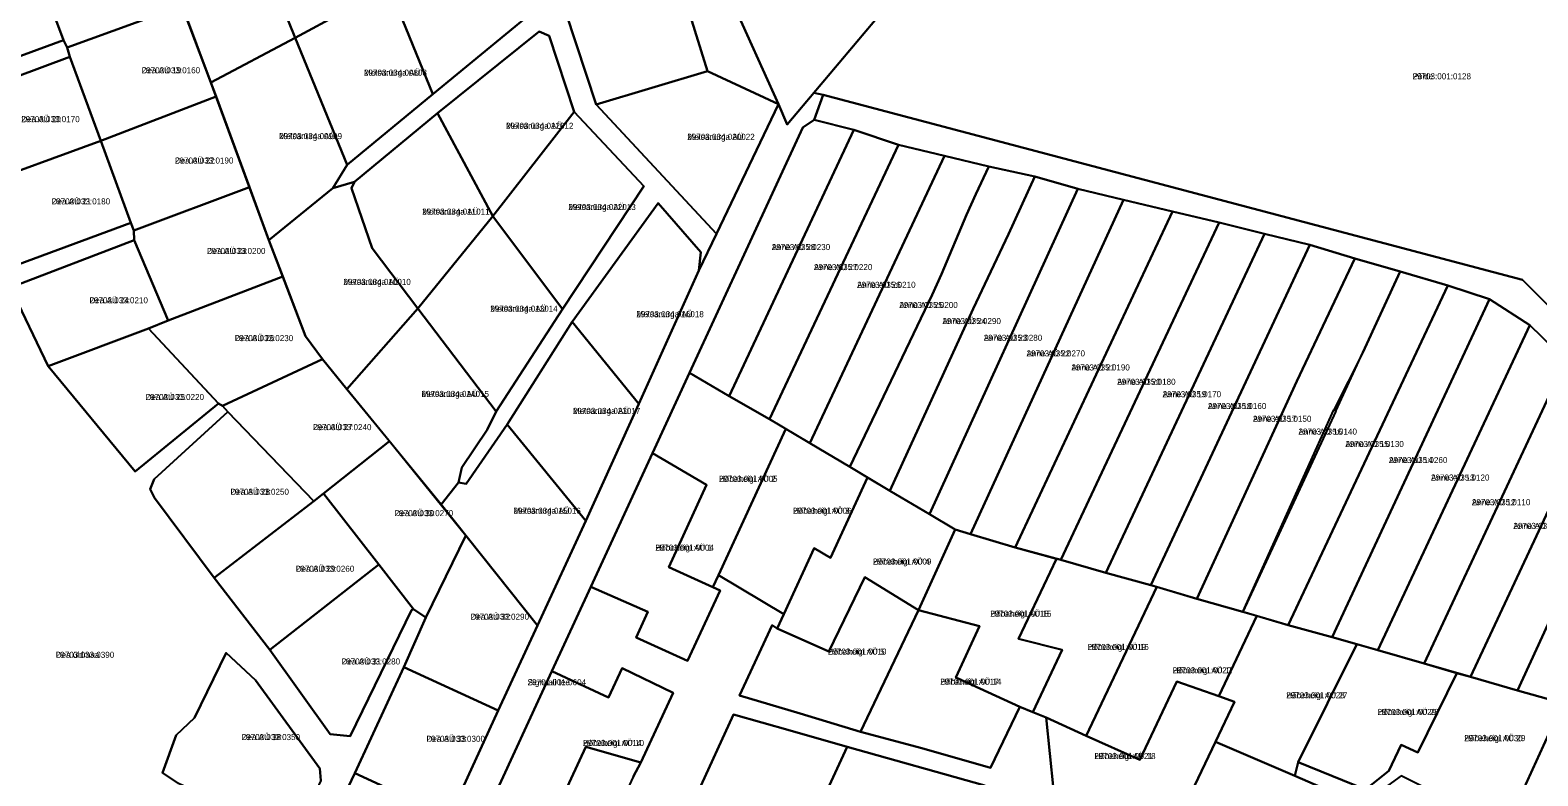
# Model space of a CAD drawing. Extents: x 504287 to 537970, y 6539941 to 6586214.
# Drawn here: x 518541.3 to 518915.2, y 6560366.3 to 6560551.4 of the extents above; entities that cross this region are included whole.
import ezdxf

# ---------------------------------------------------------------- set-up
doc = ezdxf.new("R2010")
doc.units = 0
for name, color, linetype in [('L_AADRESS', 7, 'Continuous'), ('PIIR', 7, 'Continuous'), ('TUNNUS', 7, 'Continuous')]:
    doc.layers.add(name, color=color, linetype=linetype)

msp = doc.modelspace()

# ---------------------------------------------------------------- linework, layer by layer
at = {"layer": 'PIIR'}
for points in [[(518652.65, 6560733.81), (518738.83, 6560735.38), (518768.89, 6560651.51), (518836.98, 6560656.24), (518729.02, 6560528.02), (518726.84, 6560533.06), (518680.26, 6560636.35), (518582.38, 6560628.09), (518581.74, 6560638.53), (518567.45, 6560635.3), (518576.36, 6560731.36)], [(519044.14, 6560671.72), (519015.49, 6560406.67), (518970.14, 6560431.7), (518959.47, 6560439.36), (518957.6, 6560442.94), (518911.37, 6560489.4), (518737.92, 6560535.32), (518735.63, 6560535.87), (518836.98, 6560656.24), (518890.66, 6560660.58)], [(518680.26, 6560636.35), (518726.84, 6560533.06), (518709.24, 6560541.19), (518699.85, 6560571.56), (518690.71, 6560600.29), (518681.74, 6560628.36), (518653.33, 6560625.81), (518651.06, 6560633.89)], [(518594.15, 6560581.53), (518620.85, 6560589.68), (518630.3, 6560562.19), (518607, 6560549.49)], [(518571.17, 6560578.12), (518588.78, 6560582.73), (518594.15, 6560581.53), (518607, 6560549.49), (518586.13, 6560538.4)], [(518570.54, 6560579.83), (518571.17, 6560578.12), (518578.95, 6560557.46), (518550.43, 6560547.09), (518549.54, 6560548.94), (518542.01, 6560569.21)], [(518630.3, 6560562.19), (518660.95, 6560578.68), (518667.13, 6560557.74), (518665.26, 6560555.4), (518641.13, 6560535.55)], [(518671.62, 6560563.35), (518699.85, 6560571.56), (518709.24, 6560541.19), (518681.68, 6560532.97)], [(518510.38, 6560557.54), (518539.53, 6560568.37), (518542.01, 6560569.21), (518549.54, 6560548.94), (518517.73, 6560537.23)], [(518607, 6560549.49), (518630.3, 6560562.19), (518641.13, 6560535.55), (518619.9, 6560517.97)], [(518551.09, 6560544.8), (518550.43, 6560547.09), (518578.95, 6560557.46), (518586.13, 6560538.4), (518587.42, 6560534.89), (518558.82, 6560523.93)], [(518586.13, 6560538.4), (518607, 6560549.49), (518619.9, 6560517.97), (518616.36, 6560512.18), (518600.49, 6560499.28)], [(518642.34, 6560530.81), (518667.51, 6560551.06), (518670.01, 6560550), (518676.23, 6560531.13), (518656.02, 6560505.19)], [(518519.54, 6560532.6), (518524.22, 6560534.79), (518551.09, 6560544.8), (518558.82, 6560523.93), (518527.08, 6560512.32)], [(518709.24, 6560541.19), (518726.84, 6560533.06), (518711.5, 6560500.83), (518681.68, 6560532.97)], [(518566.29, 6560503.6), (518558.82, 6560523.93), (518587.42, 6560534.89), (518595.68, 6560512.4), (518567.03, 6560501.7)], [(518626.14, 6560497.31), (518620.99, 6560512.17), (518621.74, 6560513.71), (518642.34, 6560530.81), (518656.02, 6560505.19), (518637.45, 6560482.3)], [(518656.02, 6560505.19), (518676.23, 6560531.13), (518693.48, 6560512.65), (518673.35, 6560482.14)], [(518704.81, 6560466.36), (518732.9, 6560527.21), (518735.69, 6560529.13), (518745.58, 6560526.65), (518714.64, 6560460.56)], [(518714.64, 6560460.56), (518745.58, 6560526.65), (518756.67, 6560522.93), (518724.67, 6560454.85)], [(518534.3, 6560492.74), (518527.08, 6560512.32), (518558.82, 6560523.93), (518566.29, 6560503.6), (518536.06, 6560492.38)], [(518724.67, 6560454.85), (518756.67, 6560522.93), (518768.08, 6560520.21), (518734.67, 6560448.85)], [(518734.67, 6560448.85), (518768.08, 6560520.21), (518779.01, 6560517.55), (518775.86, 6560510.72), (518773.47, 6560505.55), (518767.34, 6560490.86), (518764.96, 6560485.68), (518744.59, 6560443.03)], [(518744.59, 6560443.03), (518764.96, 6560485.68), (518767.34, 6560490.86), (518773.47, 6560505.55), (518775.86, 6560510.72), (518779.01, 6560517.55), (518790.49, 6560515.05), (518783.91, 6560500.78), (518775.17, 6560482.22), (518754.5, 6560437.02)], [(518754.5, 6560437.02), (518775.17, 6560482.22), (518783.91, 6560500.78), (518790.49, 6560515.05), (518801.08, 6560511.99), (518764.34, 6560431.24)], [(518567.07, 6560499.24), (518567.03, 6560501.7), (518595.68, 6560512.4), (518600.49, 6560499.28), (518603.94, 6560490.25), (518575.55, 6560479.31)], [(518613.8, 6560469.75), (518609.6, 6560475.44), (518600.49, 6560499.28), (518616.36, 6560512.18), (518621.74, 6560513.71), (518620.99, 6560512.17), (518626.14, 6560497.31), (518637.45, 6560482.3), (518619.86, 6560462.33)], [(518770.67, 6560427.42), (518764.34, 6560431.24), (518801.08, 6560511.99), (518812.44, 6560509.31), (518774.47, 6560426.3)], [(518697.06, 6560508.42), (518707.59, 6560496.29), (518707.15, 6560491.75), (518692.22, 6560458.64), (518675.67, 6560479.01)], [(518774.47, 6560426.3), (518812.44, 6560509.31), (518824.58, 6560506.39), (518785.58, 6560422.96)], [(518656.02, 6560505.19), (518673.35, 6560482.14), (518656.83, 6560456.71), (518637.45, 6560482.3)], [(518785.58, 6560422.96), (518824.58, 6560506.39), (518836.14, 6560503.63), (518796.88, 6560419.89)], [(518796.88, 6560419.89), (518836.14, 6560503.63), (518847.42, 6560500.85), (518808.08, 6560416.73)], [(518808.08, 6560416.73), (518847.42, 6560500.85), (518858.66, 6560498.13), (518819.25, 6560413.63)], [(518536.41, 6560487.5), (518567.07, 6560499.24), (518575.55, 6560479.31), (518570.63, 6560477.35), (518545.74, 6560467.99)], [(518819.25, 6560413.63), (518858.66, 6560498.13), (518869.82, 6560494.75), (518855.41, 6560464.24), (518830.65, 6560410.26)], [(518830.65, 6560410.26), (518855.41, 6560464.24), (518869.82, 6560494.75), (518881.04, 6560491.52), (518871.84, 6560471.37), (518864.62, 6560457.17), (518865.07, 6560456.86), (518842.05, 6560406.99)], [(518587.96, 6560458.72), (518570.63, 6560477.35), (518575.55, 6560479.31), (518603.94, 6560490.25), (518609.6, 6560475.44), (518613.8, 6560469.75), (518589.01, 6560458.16)], [(518842.05, 6560406.99), (518864.62, 6560457.17), (518865.07, 6560456.86), (518871.84, 6560471.37), (518881.04, 6560491.52), (518892.89, 6560488.03), (518853.32, 6560403.74)], [(518853.32, 6560403.74), (518892.89, 6560488.03), (518903.22, 6560484.64), (518864.2, 6560400.76)], [(518637.45, 6560482.3), (518656.83, 6560456.71), (518654.62, 6560452.19), (518648.35, 6560442.83), (518647.52, 6560439.11), (518643.18, 6560433.67), (518619.86, 6560462.33)], [(518864.2, 6560400.76), (518903.22, 6560484.64), (518913.23, 6560478.2), (518875.53, 6560397.55)], [(518675.67, 6560479.01), (518692.22, 6560458.64), (518679.09, 6560429.64), (518659.55, 6560453.54)], [(518875.53, 6560397.55), (518913.23, 6560478.2), (518922.14, 6560469.49), (518886.99, 6560394.2)], [(518570.63, 6560477.35), (518587.96, 6560458.72), (518567.36, 6560441.84), (518545.74, 6560467.99)], [(518590.27, 6560456.69), (518589.01, 6560458.16), (518613.8, 6560469.75), (518619.86, 6560462.33), (518630.42, 6560449.4), (518614.03, 6560436.37), (518611.67, 6560434.49)], [(518714.64, 6560460.56), (518724.67, 6560454.85), (518728.68, 6560452.44), (518711.96, 6560416.15), (518710.56, 6560413.13), (518699.64, 6560418.11), (518709.06, 6560438.54), (518695.6, 6560446.38), (518704.81, 6560466.36)], [(518886.99, 6560394.2), (518922.14, 6560469.49), (518931.28, 6560460.86), (518898.48, 6560390.85)], [(518898.48, 6560390.85), (518931.28, 6560460.86), (518939.85, 6560452.15), (518910.17, 6560387.5)], [(518572.14, 6560435.35), (518571.07, 6560437.47), (518572.02, 6560439.92), (518590.27, 6560456.69), (518611.67, 6560434.49), (518586.89, 6560415.45)], [(518647.52, 6560439.11), (518649.44, 6560438.81), (518659.55, 6560453.54), (518679.09, 6560429.64), (518667.09, 6560403.65), (518643.18, 6560433.67)], [(518734.67, 6560448.85), (518744.59, 6560443.03), (518748.99, 6560440.36), (518739.74, 6560420.4), (518735.72, 6560422.81), (518728.24, 6560406.48), (518711.96, 6560416.15), (518728.68, 6560452.44)], [(518910.17, 6560387.5), (518939.85, 6560452.15), (518948.27, 6560440.01), (518921.41, 6560384.38)], [(518614.03, 6560436.37), (518630.42, 6560449.4), (518649.34, 6560425.93), (518639.39, 6560405.63), (518636.38, 6560407.67), (518627.76, 6560418.77)], [(518695.6, 6560446.38), (518709.06, 6560438.54), (518699.64, 6560418.11), (518710.56, 6560413.13), (518712.38, 6560412.29), (518704.31, 6560394.84), (518691.57, 6560400.65), (518694.51, 6560407), (518680.32, 6560413.23)], [(518754.5, 6560437.02), (518764.34, 6560431.24), (518770.67, 6560427.42), (518761.6, 6560407.45), (518748.32, 6560415.6), (518739.36, 6560397.16), (518726.57, 6560402.85), (518728.24, 6560406.48), (518735.72, 6560422.81), (518739.74, 6560420.4), (518748.99, 6560440.36)], [(518586.89, 6560415.45), (518611.67, 6560434.49), (518614.03, 6560436.37), (518627.76, 6560418.77), (518600.7, 6560397.57)], [(518639.39, 6560405.63), (518649.34, 6560425.93), (518667.09, 6560403.65), (518657.34, 6560382.53), (518633.92, 6560393.33)], [(518774.47, 6560426.3), (518785.58, 6560422.96), (518795.84, 6560420.17), (518786.4, 6560400.3), (518797.22, 6560397.63), (518789.99, 6560382.08), (518786.77, 6560383.45), (518770.87, 6560390.76), (518776.77, 6560403.46), (518761.6, 6560407.45), (518770.67, 6560427.42)], [(518600.7, 6560397.57), (518627.76, 6560418.77), (518636.38, 6560407.67), (518635.82, 6560407.45), (518620.67, 6560376.18), (518615.7, 6560376.63)], [(518796.88, 6560419.89), (518808.08, 6560416.73), (518819.25, 6560413.63), (518820.7, 6560413.2), (518803.15, 6560376.28), (518793.26, 6560380.83), (518789.99, 6560382.08), (518797.22, 6560397.63), (518786.4, 6560400.3), (518795.84, 6560420.17)], [(518726.57, 6560402.85), (518739.36, 6560397.16), (518748.32, 6560415.6), (518761.6, 6560407.45), (518747.23, 6560377.21), (518732.23, 6560381.8), (518717.19, 6560386.27), (518725.34, 6560403.71)], [(518830.65, 6560410.26), (518842.05, 6560406.99), (518845.49, 6560405.99), (518836.1, 6560386.09), (518825.65, 6560389.77), (518816.49, 6560370.32), (518803.15, 6560376.28), (518820.7, 6560413.2)], [(518776.77, 6560403.46), (518770.87, 6560390.76), (518786.77, 6560383.45), (518779.44, 6560368.31), (518762.39, 6560373.16), (518747.23, 6560377.21), (518761.6, 6560407.45)], [(518853.32, 6560403.74), (518864.2, 6560400.76), (518870.35, 6560399.02), (518855.79, 6560369.73), (518854.93, 6560366.34), (518835.24, 6560374.79), (518839.98, 6560384.72), (518836.1, 6560386.09), (518845.49, 6560405.99)], [(518875.53, 6560397.55), (518886.99, 6560394.2), (518895.15, 6560391.82), (518885.42, 6560372.09), (518881.34, 6560374.03), (518878.27, 6560367.52), (518872.47, 6560362.92), (518855.79, 6560369.73), (518870.35, 6560399.02)], [(518574.08, 6560367.07), (518577.52, 6560376.41), (518582.01, 6560380.74), (518589.9, 6560396.82), (518597.19, 6560390.03), (518613.13, 6560368.1), (518613.39, 6560365.17), (518607.93, 6560353.29), (518605.66, 6560352.86), (518605.14, 6560351.85), (518578.07, 6560364.39)], [(518633.92, 6560393.33), (518657.34, 6560382.53), (518645.29, 6560356.18), (518621.81, 6560366.95)], [(518684.73, 6560385.78), (518688.11, 6560393.03), (518700.72, 6560386.95), (518692.72, 6560369.61), (518679.09, 6560373.49), (518670.29, 6560354.42), (518655.2, 6560358.71), (518670.68, 6560392.32)], [(518898.48, 6560390.85), (518910.17, 6560387.5), (518921.41, 6560384.38), (518907.28, 6560353.45), (518881.27, 6560366.28), (518875.3, 6560361.91), (518872.47, 6560362.92), (518878.27, 6560367.52), (518881.34, 6560374.03), (518885.42, 6560372.09), (518895.15, 6560391.82)], [(518803.15, 6560376.28), (518816.49, 6560370.32), (518825.65, 6560389.77), (518836.1, 6560386.09), (518839.98, 6560384.72), (518835.24, 6560374.79), (518824.05, 6560351.19), (518811.04, 6560358.67), (518795.1, 6560362.92), (518793.26, 6560380.83)], [(518729.79, 6560377.53), (518743.88, 6560373.55), (518734.51, 6560353.12), (518727.57, 6560338.2), (518713.26, 6560342.33), (518720.89, 6560357.71), (518706.71, 6560361.85), (518715.68, 6560381.57)], [(518692.72, 6560369.61), (518690.85, 6560366.04), (518683.7, 6560350.58), (518679.66, 6560351.85), (518670.12, 6560331.42), (518660.35, 6560334.15), (518645.78, 6560338.28), (518655.2, 6560358.71), (518670.29, 6560354.42), (518679.09, 6560373.49)], [(518734.51, 6560353.12), (518743.88, 6560373.55), (518778.03, 6560363.92), (518768.66, 6560343.46), (518753.52, 6560347.69)], [(518854.93, 6560366.34), (518864.63, 6560362.14), (518853.89, 6560339.57), (518837.55, 6560345.86), (518824.05, 6560351.19), (518835.24, 6560374.79)], [(518621.81, 6560366.95), (518645.29, 6560356.18), (518632.92, 6560329.34), (518609.27, 6560340.6)]]:
    msp.add_lwpolyline(points, close=True, dxfattribs=at)
for points in [[(518671.62, 6560563.35), (518681.68, 6560532.97), (518711.5, 6560500.83), (518707.15, 6560491.75), (518707.59, 6560496.29), (518697.06, 6560508.42), (518675.67, 6560479.01), (518659.55, 6560453.54), (518649.44, 6560438.81), (518647.52, 6560439.11), (518648.35, 6560442.83), (518654.62, 6560452.19), (518656.83, 6560456.71), (518673.35, 6560482.14), (518693.48, 6560512.65), (518676.23, 6560531.13), (518670.01, 6560550), (518667.51, 6560551.06), (518642.34, 6560530.81), (518621.74, 6560513.71), (518616.36, 6560512.18), (518619.9, 6560517.97), (518641.13, 6560535.55), (518665.26, 6560555.4)], [(518517.73, 6560537.23), (518549.54, 6560548.94), (518550.43, 6560547.09), (518551.09, 6560544.8), (518524.22, 6560534.79)], [(518645.29, 6560356.18), (518657.34, 6560382.53), (518667.09, 6560403.65), (518679.09, 6560429.64), (518692.22, 6560458.64), (518707.15, 6560491.75), (518711.5, 6560500.83), (518726.84, 6560533.06), (518729.02, 6560528.02), (518735.63, 6560535.87), (518737.92, 6560535.32), (518735.69, 6560529.13), (518732.9, 6560527.21), (518704.81, 6560466.36), (518695.6, 6560446.38), (518680.32, 6560413.23), (518670.68, 6560392.32), (518655.2, 6560358.71)], [(518922.14, 6560469.49), (518913.23, 6560478.2), (518903.22, 6560484.64), (518892.89, 6560488.03), (518881.04, 6560491.52), (518869.82, 6560494.75), (518858.66, 6560498.13), (518847.42, 6560500.85), (518836.14, 6560503.63), (518824.58, 6560506.39), (518812.44, 6560509.31), (518801.08, 6560511.99), (518790.49, 6560515.05), (518779.01, 6560517.55), (518768.08, 6560520.21), (518756.67, 6560522.93), (518745.58, 6560526.65), (518735.69, 6560529.13), (518737.92, 6560535.32), (518911.37, 6560489.4), (518957.6, 6560442.94)], [(518536.06, 6560492.38), (518566.29, 6560503.6), (518567.03, 6560501.7), (518567.07, 6560499.24), (518536.41, 6560487.5), (518545.74, 6560467.99), (518567.36, 6560441.84), (518587.96, 6560458.72), (518589.01, 6560458.16), (518590.27, 6560456.69), (518572.02, 6560439.92), (518571.07, 6560437.47), (518572.14, 6560435.35), (518586.89, 6560415.45), (518600.7, 6560397.57), (518615.7, 6560376.63), (518620.67, 6560376.18), (518635.82, 6560407.45), (518636.38, 6560407.67), (518639.39, 6560405.63), (518633.92, 6560393.33), (518621.81, 6560366.95), (518609.27, 6560340.6)], [(518690.85, 6560366.04), (518692.72, 6560369.61), (518700.72, 6560386.95), (518688.11, 6560393.03), (518684.73, 6560385.78), (518670.68, 6560392.32), (518680.32, 6560413.23), (518694.51, 6560407), (518691.57, 6560400.65), (518704.31, 6560394.84), (518712.38, 6560412.29), (518710.56, 6560413.13), (518711.96, 6560416.15), (518728.24, 6560406.48), (518726.57, 6560402.85), (518725.34, 6560403.71), (518717.19, 6560386.27), (518732.23, 6560381.8), (518747.23, 6560377.21), (518762.39, 6560373.16), (518779.44, 6560368.31), (518786.77, 6560383.45), (518789.99, 6560382.08), (518793.26, 6560380.83), (518795.1, 6560362.92)], [(518613.39, 6560365.17), (518613.13, 6560368.1), (518597.19, 6560390.03), (518589.9, 6560396.82), (518582.01, 6560380.74), (518577.52, 6560376.41), (518574.08, 6560367.07), (518578.07, 6560364.39)], [(518917.15, 6560359.22), (518911.58, 6560346.96), (518905.86, 6560334.63), (518900.2, 6560322.05), (518893.93, 6560324.21), (518921.41, 6560384.38)], [(518778.03, 6560363.92), (518743.88, 6560373.55), (518729.79, 6560377.53), (518715.68, 6560381.57), (518706.71, 6560361.85)], [(518864.63, 6560362.14), (518854.93, 6560366.34), (518855.79, 6560369.73), (518872.47, 6560362.92)]]:
    msp.add_lwpolyline(points, dxfattribs=at)

# ---------------------------------------------------------------- texts
at = {"layer": 'L_AADRESS'}
for s, p in [('Dea AÜ 19', (518568.94, 6560540.7)), ('Metsanurga AÜ 8', (518624.07, 6560540.11)), ('Põlde', (518884.12, 6560539.2)), ('Dea AÜ 20', (518539.07, 6560528.56)), ('Metsanurga AÜ 9', (518603.02, 6560524.35)), ('Metsanurga AÜ 12', (518659.29, 6560526.91)), ('Metsanurga AÜ 22', (518704.26, 6560524.17)), ('Dea AÜ 22', (518577.2, 6560518.29)), ('Dea AÜ 21', (518546.62, 6560508.15)), ('Metsanurga AÜ 11', (518638.51, 6560505.61)), ('Metsanurga AÜ 13', (518674.75, 6560506.75)), ('Dea AÜ 23', (518585.15, 6560495.85)), ('Anne AÜ 28', (518725.2, 6560496.81)), ('Anne AÜ 27', (518735.66, 6560491.84)), ('Metsanurga AÜ 10', (518618.97, 6560488.17)), ('Anne AÜ 26', (518746.38, 6560487.44)), ('Dea AÜ 24', (518555.99, 6560483.61)), ('Metsanurga AÜ 14', (518655.4, 6560481.51)), ('Metsanurga AÜ 18', (518691.63, 6560480.16)), ('Anne AÜ 25', (518756.84, 6560482.44)), ('Anne AÜ 24', (518767.54, 6560478.44)), ('Dea AÜ 26', (518592.03, 6560474.21)), ('Anne AÜ 23', (518777.79, 6560474.29)), ('Anne AÜ 22', (518788.39, 6560470.42)), ('Anne AÜ 21', (518799.52, 6560466.93)), ('Anne AÜ 20', (518810.86, 6560463.37)), ('Dea AÜ 25', (518569.91, 6560459.6)), ('Metsanurga AÜ 15', (518638.34, 6560460.37)), ('Anne AÜ 19', (518822.15, 6560460.3)), ('Anne AÜ 18', (518833.37, 6560457.36)), ('Metsanurga AÜ 17', (518675.88, 6560456.15)), ('Anne AÜ 17', (518844.54, 6560454.19)), ('Dea AÜ 27', (518611.44, 6560452.12)), ('Anne AÜ 16', (518855.84, 6560451.02)), ('Anne AÜ 15', (518867.47, 6560447.94)), ('Anne AÜ 14', (518878.27, 6560443.95)), ('Hõbeheigi AÜ 2', (518712.14, 6560439.29)), ('Anne AÜ 13', (518888.71, 6560439.61)), ('Dea AÜ 28', (518590.96, 6560436.07)), ('Dea AÜ 30', (518631.69, 6560430.77)), ('Metsanurga AÜ 16', (518661.14, 6560431.36)), ('Hõbeheigi AÜ 3', (518730.48, 6560431.36)), ('Anne AÜ 12', (518898.84, 6560433.49)), ('Anne AÜ 11', (518909.14, 6560427.61)), ('Hõbeheigi AÜ 1', (518696.35, 6560422.21)), ('Dea AÜ 29', (518607.17, 6560416.97)), ('Hõbeheigi AÜ 4', (518750.3, 6560418.76)), ('Dea AÜ 32', (518650.51, 6560405.07)), ('Hõbeheigi AÜ 15', (518779.41, 6560405.82)), ('Hõbeheigi AÜ 16', (518803.55, 6560397.56)), ('Dea üldmaa', (518547.64, 6560395.61)), ('Dea AÜ 31', (518618.54, 6560393.96)), ('Hõbeheigi AÜ 5', (518739.14, 6560396.41)), ('Hõbeheigi AÜ 17', (518824.64, 6560391.76)), ('Signaali tee', (518664.66, 6560388.81)), ('Hõbeheigi AÜ 14', (518767, 6560388.94)), ('Hõbeheigi AÜ 27', (518852.8, 6560385.57)), ('Hõbeheigi AÜ 28', (518875.47, 6560381.43)), ('Dea AÜ 38', (518593.73, 6560375.19)), ('Dea AÜ 33', (518639.58, 6560374.76)), ('Hõbeheigi AÜ 29', (518896.94, 6560374.92)), ('Hõbeheigi AÜ 10', (518678.37, 6560373.73)), ('Hõbeheigi AÜ 18', (518805.23, 6560370.48))]:
    msp.add_text(s, height=1.5, dxfattribs=at).set_placement(p)
at = {"layer": 'TUNNUS'}
for s, p in [('29703:033:0160', (518568.94, 6560540.7)), ('29703:034:0080', (518624.07, 6560540.11)), ('29703:001:0128', (518884.12, 6560539.2)), ('29703:033:0170', (518539.07, 6560528.56)), ('29703:034:0120', (518659.29, 6560526.91)), ('29703:034:0090', (518603.02, 6560524.35)), ('29703:034:0200', (518704.26, 6560524.17)), ('29703:033:0190', (518577.2, 6560518.29)), ('29703:033:0180', (518546.62, 6560508.15)), ('29703:034:0220', (518674.75, 6560506.75)), ('29703:034:0110', (518638.51, 6560505.61)), ('29703:033:0200', (518585.15, 6560495.85)), ('29703:035:0230', (518725.2, 6560496.81)), ('29703:035:0220', (518735.66, 6560491.84)), ('29703:034:0100', (518618.97, 6560488.17)), ('29703:035:0210', (518746.38, 6560487.44)), ('29703:033:0210', (518555.99, 6560483.61)), ('29703:034:0130', (518655.4, 6560481.51)), ('29703:034:0160', (518691.63, 6560480.16)), ('29703:035:0200', (518756.84, 6560482.44)), ('29703:035:0290', (518767.54, 6560478.44)), ('29703:033:0230', (518592.03, 6560474.21)), ('29703:035:0280', (518777.79, 6560474.29)), ('29703:035:0270', (518788.39, 6560470.42)), ('29703:035:0190', (518799.52, 6560466.93)), ('29703:035:0180', (518810.86, 6560463.37)), ('29703:033:0220', (518569.91, 6560459.6)), ('29703:034:0140', (518638.34, 6560460.37)), ('29703:035:0170', (518822.15, 6560460.3)), ('29703:035:0160', (518833.37, 6560457.36)), ('29703:034:0230', (518675.88, 6560456.15)), ('29703:035:0150', (518844.54, 6560454.19)), ('29703:033:0240', (518611.44, 6560452.12)), ('29703:035:0140', (518855.84, 6560451.02)), ('29703:035:0130', (518867.47, 6560447.94)), ('29703:035:0260', (518878.27, 6560443.95)), ('29703:001:0005', (518712.14, 6560439.29)), ('29703:035:0120', (518888.71, 6560439.61)), ('29703:033:0250', (518590.96, 6560436.07)), ('29703:034:0150', (518661.14, 6560431.36)), ('29703:001:0006', (518730.48, 6560431.36)), ('29703:035:0110', (518898.84, 6560433.49)), ('29703:033:0270', (518631.69, 6560430.77)), ('29703:035:0100', (518909.14, 6560427.61)), ('29703:001:0004', (518696.35, 6560422.21)), ('29703:033:0260', (518607.17, 6560416.97)), ('29703:001:0009', (518750.3, 6560418.76)), ('29703:033:0290', (518650.51, 6560405.07)), ('29703:001:0018', (518779.41, 6560405.82)), ('29703:001:0019', (518803.55, 6560397.56)), ('29703:033:0390', (518547.64, 6560395.61)), ('29703:033:0280', (518618.54, 6560393.96)), ('29703:001:0010', (518739.14, 6560396.41)), ('29703:001:0020', (518824.64, 6560391.76)), ('29701:001:0604', (518664.66, 6560388.81)), ('29703:001:0017', (518767, 6560388.94)), ('29703:001:0028', (518852.8, 6560385.57)), ('29703:001:0029', (518875.47, 6560381.43)), ('29703:033:0350', (518593.73, 6560375.19)), ('29703:033:0300', (518639.58, 6560374.76)), ('29703:001:0014', (518678.37, 6560373.73)), ('29703:001:0030', (518896.94, 6560374.92)), ('29703:001:0021', (518805.23, 6560370.48))]:
    msp.add_text(s, height=1.5, dxfattribs=at).set_placement(p)

doc.saveas('drawing.dxf')
